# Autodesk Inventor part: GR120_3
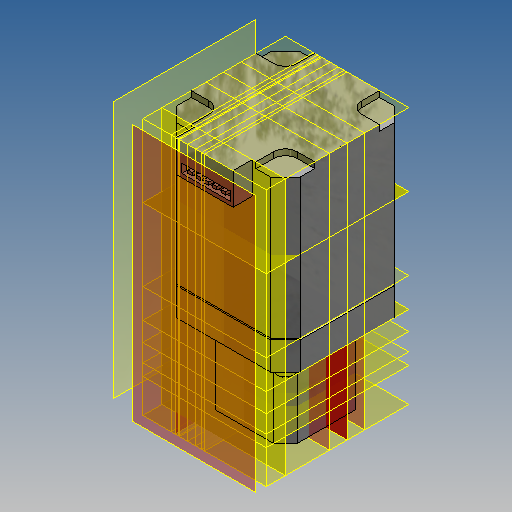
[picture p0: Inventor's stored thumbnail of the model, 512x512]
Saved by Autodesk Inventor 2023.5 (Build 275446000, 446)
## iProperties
Part Number: GR120_3
Material: Allgemein
Document SubType Name: Modellieren
Designer: WH
Appearance: Vorgabe
Author: WH
NB: GR120_3
NN: GR120-OS
NBSYN: $CNSORDERNO._3
LINA: GR120_3
CATALOG: GIGAGER
CNSORDERNO: GR120
SCS: GR120
SUPPLIER: SAINI
ARTICLENO: GR120_3
BOMINFO: GR120_3
CREATOR: CADENAS GmbH
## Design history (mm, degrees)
feature "GR120_3"
node "A_1"
node "A_2"
node "A_3"
node "A_4"
node "A_5"
node "A_6"
node "A_7"
node "A_8"
node "A_9"
node "A_10"
node "A_11"
node "A_12"
node "A_13"
node "3_ZAXS"
node "33_ZAXS"
node "RIGHT"
node "TOP"
node "FRONT"
node "DTM1"
node "DTM2"
node "DTM3"
node "DTM4"
node "DTM5"
node "DTM6"
node "DTM7"
node "DTM8"
node "DTM9"
node "DTM10"
node "DTM11"
node "DTM12"
node "DTM13"
node "DTM14"
node "DTM15"
node "DTM16"
node "DTM17"
node "DTM18"
node "DTM19"
node "DTM20"
node "DTM21"
node "DTM22"
node "DTM23"
node "DTM24"
node "DTM25"
node "DTM26"
node "DTM27"
node "DTM28"
node "DTM29"
node "DTM30"
node "DTM31"
node "DTM32"
node "DTM33"
node "DTM34"
node "DTM35"
node "DTM36"
node "DTM37"
node "DTM38"
node "DTM39"
node "DTM40"
node "DTM41"
node "DTM42"
node "DTM43"
node "DTM44"
node "DTM45"
node "DTM46"
node "DTM47"
node "DTM48"
node "DTM49"
node "DTM50"
node "DTM51"
node "DTM52"
node "DTM53"
node "DTM54"
node "DTM55"
node "3_XPLN"
node "3_YPLN"
node "3_ZPLN"
node "33_XPLN"
node "33_YPLN"
node "33_ZPLN"
node "Volumenkörper1"
node "Volumenkörper"
node "Flächenkörper"
